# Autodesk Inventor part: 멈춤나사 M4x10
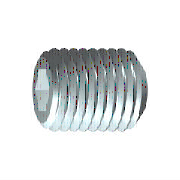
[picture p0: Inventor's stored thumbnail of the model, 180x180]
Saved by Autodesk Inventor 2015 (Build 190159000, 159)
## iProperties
Created: 2012-02
Part Number: 멈춤나사 M4x10
Material: 강철, 연강
Description: 6각 소켓 머리 없는 멈춤 나사
Document SubType Name: Modeling
Standard: KS B 1028
Designer: mduedu
Standards Organization: KS
Language: ko-KR
Size Designation: 납작점M4x10
Categories: <MemberInstance><Categories><Category DisplayName="조임쇠" InternalName="e4da775c-781d-43d5-af7c-5136215cf5a6" Mnemonic="FSTN"><Category DisplayName="볼트" InternalN
Density: 1 g/cm^3
Appearance: 강철
IsCustomPart: 1
Author: mduedu
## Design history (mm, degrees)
sketch "스케치1"
  geometry: L1 (0, 0)-(6.833, 0); L2 (10, 1.155)-(10, 2); L3 (10, 2)-(0, 2); L4 (10, 1.155)-(7.5, 1.155); L5 (7.5, 1.155)-(6.833, 0); L6 (0, -0.4)-(0, 2.4) reference; L7 (0, 2)-(0, 0)
  constraints: 13 end point, 3 parallel, 1 collinear, 1 perpendicular, 1 point on line
  dimensions: "d0" = 2.5 distance of L2.start L4.end (= INTI); "d1" = 60 deg angle of L5 L1; "d2" = 4 diameter of L3 L1 (= NND); "d3" = 2.3094 diameter of L4 L1 (= 1.1547 x SW); "d5" = 10 distance from line of L2 L3.end (= NLG)
revolve "본체" sketch "스케치1" stored, may be unused: angle "d6" = 90 deg
sketch "스케치2"
  geometry: L1 (-0.577, 1)-(0.577, 1); L2 (0.577, 1)-(1.155, 0); L3 (1.155, 0)-(0.577, -1); L4 (0.577, -1)-(-0.577, -1); L5 (-0.577, -1)-(-1.155, 0); L6 (-1.155, 0)-(-0.577, 1); A1 r 1.155 centre (0, 0) between (-0.577, 1) and (0.577, 1) reference; 2 further points
  constraints: 12 end point, 2 point on circle, 1 coincident, 1 horizontal, 11 other
extrude "슬롯" join sketch "스케치2" taper "d9" = 0 deg; stored distance "d21" = 10
workaxis "Work Axis1"
workplane "Work Plane1"
body "Solid1"
chamfer "모따기1" distance "d7" = 0.42941 (= -0.5 x GD1 + 0.5 x NND); stored, may be unused: angle "d8" = 45 deg (= FAWI), second distance "d29" = 0.42941 (= -0.5 x GD1 + 0.5 x NND)
feature "스레드" dims "d11" = 10 (= NLG), "d12" = 0
chamfer "모따기2" distance "d13" = 0.42941 (= -0.5 x GD1 + 0.5 x NND); stored, may be unused: angle "d14" = 45 deg (= FAWI), second distance "d30" = 0.42941 (= -0.5 x GD1 + 0.5 x NND)
other parameters: "NND" = 4 [user parameter; used in 5 equation terms], "NLG" = 10 [user parameter; used in 2 equation terms], "INTI" = 2.5 [user parameter; used in 1 equation term], "FAWI" = 45 deg [user parameter; used in 2 equation terms], "SW" = 2 [user parameter; used in 2 equation terms], "GD1" = 3.14117 (= THREADDIA - 1.2269 x PTC) [user parameter; used in 4 equation terms], "d4" = 0, "FAWI1" = 45 deg [user parameter], "d15" = 0, "d31" = 0, "GUL" = 0.42941 (= 0.61345 x PTC) [user parameter], "SPD" = 2.5 [user parameter], "TPU" = 14.28571 (computed from PTC) [user parameter], "TOA" = 30 deg [user parameter], "THREADDIA" = 4 [user parameter; used in 1 equation term], "PTC" = 0.7 [user parameter; used in 4 equation terms], "GAL" = 0.42941 (= 0.61345 x PTC) [user parameter], "E0" = 2.31 (= 1.155 x SW) [user parameter]
